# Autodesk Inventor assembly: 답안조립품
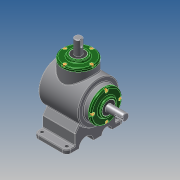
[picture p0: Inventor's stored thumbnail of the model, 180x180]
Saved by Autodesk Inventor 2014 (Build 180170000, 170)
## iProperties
Created: 2018-08
Part Number: 답안조립품
Document SubType Name: Assembly
Designer: kb542
Author: kb542
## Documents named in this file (14)
- C:\Users\kb542\Desktop\480807V1019\답안조립품.iam
- C:\Users\kb542\Desktop\480807V1019\본체.ipt
- C:\Users\kb542\Desktop\480807V1019\커버.ipt
- C:\Users\kb542\Desktop\480807V1019\베어링 6203.ipt
- C:\Users\kb542\Desktop\480807V1019\메인 축.ipt
- 메인 축.ipt
- C:\Users\kb542\Desktop\480807V1019\오일실 17 32 8.ipt
- C:\Users\kb542\Desktop\480807V1019\키 5x5.ipt
- C:\Users\kb542\Desktop\480807V1019\메인 베벨기어.ipt
- C:\Users\kb542\Desktop\480807V1019\서브 축.ipt
- 서브 축.ipt
- C:\Users\kb542\Desktop\480807V1019\키 4x4.ipt
- C:\Users\kb542\Desktop\480807V1019\서브 베벨기어.ipt
- C:\Users\kb542\Desktop\480807V1019\볼트 M4.ipt
